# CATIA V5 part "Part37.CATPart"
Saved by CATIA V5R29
Part number: spur gear_iso_ISO - Spur gear 0.5M 56T 20PA 7FW ---S56A75H50L16.0N
Revision: ANY
Definition: UNKNOWN
Nomenclature: spur gear_iso_ISO - Spur gear 0.5M 56T 20PA 7FW ---S56A75H50L16.0N
Source: Unknown
Bounding box of the stored display mesh (mm): x 0 to 7, y -14.485 to 14.485, z -14.485 to 14.485
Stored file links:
  C:\Users\Administrator\Desktop\프로젝트\Gripper\Part37.CATPart
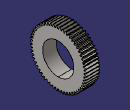
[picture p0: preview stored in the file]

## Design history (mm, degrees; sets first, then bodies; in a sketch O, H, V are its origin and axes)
Body1 "Bore" (main body)
  Solid1: solid without history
